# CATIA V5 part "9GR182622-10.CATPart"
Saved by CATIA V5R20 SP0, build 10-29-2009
Part number: 9GR182622-10
Revision: ANY
Definition: UNKNOWN
Nomenclature: 9GR182622-10
Source: Unknown
Bounding box of the stored display mesh (mm): x -10.897 to 10.833, y -21 to 5, z -11 to 11
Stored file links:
  C:\Users\Utente\Desktop\IO LAVORO\3D X SITO CF\CUMSA\3D files GR\GR 182622-10\9GR182622-10.CATPart
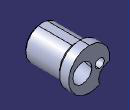
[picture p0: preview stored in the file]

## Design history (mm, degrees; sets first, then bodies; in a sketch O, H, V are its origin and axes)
Body1 "Cortar-Extruir7" (main body)
  Solid1: solid without history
